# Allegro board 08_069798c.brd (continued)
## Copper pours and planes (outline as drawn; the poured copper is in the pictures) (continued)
EXT_VDDLDO on TOP: 35.07,63.68 35.07,61.61 34.81,61.36 32.97,61.36 32.84,61.23 32.84,60.41 33.03,60.21 36.59,60.21 36.72,60.34 36.72,63.68
EXT_VIO1V1 on TOP: 40.15,65.61 40.15,61.55 39.89,61.29 38.05,61.29 37.92,61.17 37.92,60.34 38.11,60.15 41.67,60.15 41.8,60.28 41.8,65.68 40.21,65.68
FMC_VADJ on TOP (solid shape): 80.78,42.63 81.13,42.63 81.13,42.17 79.84,42.17 79.61,42.4 79.61,42.72 79.78,42.89 80.53,42.89
FMC_VADJ on TOP (solid shape): 80.74,38.95 81.13,38.95 81.13,38.44 80.73,38.44 80.48,38.19 80.1,38.19 79.98,38.32 79.98,39.14 80.04,39.21 80.49,39.21
FMC_VADJ on TOP (solid shape): 80.74,27.41 81.13,27.41 81.13,26.9 80.73,26.9 80.48,26.65 80.1,26.65 79.98,26.78 79.98,27.6 80.04,27.67 80.49,27.67
FMC_VADJ on TOP (solid shape): 80.74,23.73 81.13,23.73 81.13,23.22 80.73,23.22 80.48,22.97 80.1,22.97 79.98,23.1 79.98,23.92 80.04,23.99 80.49,23.99
FMC_VADJ on BOTTOM (solid shape): 80.74,38.95 81.13,38.95 81.13,38.44 80.73,38.44 80.48,38.19 80.1,38.19 79.98,38.32 79.98,39.14 80.04,39.21 80.49,39.21
FMC_VADJ on BOTTOM (solid shape): 80.74,27.41 81.13,27.41 81.13,26.9 80.73,26.9 80.48,26.65 80.1,26.65 79.98,26.78 79.98,27.6 80.04,27.67 80.49,27.67
FMC_VADJ on BOTTOM (solid shape): 80.74,23.73 81.13,23.73 81.13,23.22 80.73,23.22 80.48,22.97 80.1,22.97 79.98,23.1 79.98,23.92 80.04,23.99 80.49,23.99
FMC_VADJ on TOP, BOTTOM: 81.13,35.27 80.74,35.27 80.49,35.53 80.04,35.53 79.98,35.47 79.98,34.64 80.1,34.51 80.48,34.51 80.73,34.76 81.13,34.76
FMC_VADJ on TOP, BOTTOM: 81.13,30.58 80.78,30.58 80.53,30.32 79.78,30.32 79.61,30.48 79.61,30.8 79.84,31.03 81.13,31.03
FMC_VADJ on TOP, BOTTOM: 81.13,46.3 80.74,46.3 80.49,46.56 80.04,46.56 79.98,46.5 79.98,45.67 80.1,45.55 80.48,45.55 80.73,45.8 81.13,45.8
FMC_VADJ on BOTTOM: 81.13,42.63 80.78,42.63 80.53,42.89 79.78,42.89 79.61,42.72 79.61,42.4 79.84,42.17 81.13,42.17
FMC_VADJ on L5_SECONDARY_POWER: outline of 127 points within 0.64,0.64 97.34,58.1 ; 1 cut-out
IOVDD on TOP: 70.14,35.48 70.14,35.93 70.02,36.05 70.02,36.82 70.09,36.88 71.04,36.88 71.17,36.75 71.17,36.43 71.04,36.31 70.72,36.31 70.59,36.18 70.59,35.99 70.5,35.89 70.5,35.48
IOVDD on BOTTOM: 70.09,35.74 72.12,35.74 72.12,36.56 76.44,36.56 76.44,40.82 73.9,40.82 73.9,37.39 70.78,37.39 70.78,37.58 70.09,37.58
IOVDD on L3_PRIMARY_POWER: 70.02,37.26 71.67,37.26 71.67,35.35 72.83,35.35 72.83,31.09 73.01,30.91 87.04,30.91 87.04,24.31 81.39,18.65 81.39,15.23 82.47,14.15 83.36,14.15 83.55,13.96 83.55,13.26 83.42,13.13 77.77,13.13 76.56,14.34 76.56,26.49 74.54,28.51 70.02,28.51
LDO_IN_VDD1V1 on TOP: 19.41,50.85 19.41,48.37 20.62,48.37 20.62,49.96 20.3,50.28 20.3,50.79 20.24,50.85
LDO_IN_VDD1V1 on TOP: 27.76,59.36 27.76,57.04 28.97,57.04 28.97,59.36
LDO_IN_VDD1V1 on TOP: 16.37,52.37 16.37,54.6 13.44,54.6 13.25,54.4 13.25,53.58 11.48,53.58 11.35,53.45 11.35,52.44 11.41,52.37
LDO_IN_VDD1V1 on BOTTOM: 13.51,52.5 13.51,55.67 13.76,55.93 25.83,55.93 25.86,55.9 25.86,55.96 28.05,58.15 29.13,58.15 29.19,58.09 29.19,56.75 26.49,54.06 24.14,54.06 24.18,54.02 20.81,54.02 20.68,53.9 20.68,48.56 20.62,48.5 19.41,48.5 19.41,53.9 19.54,54.02 19.48,54.09 14.84,54.09 14.71,53.96 14.71,52.44 13.57,52.44
LDO_IN_VDD1V1 on L5_SECONDARY_POWER: 29.07,56.82 29.07,58.85 27.35,60.56 16.62,60.56 13.44,57.39 13.44,52.63 14.02,52.06 14.97,52.06 15.1,52.18 15.1,56.5 16.87,58.28 26.65,58.28 27.6,57.33 27.6,56.75 27.73,56.63 28.87,56.63
LDO_IN_VDD3V3 on TOP: 51.8,18.27 51.8,17.26 51.86,17.19 53.07,17.19 53.13,17.26 53.7,17.26 53.83,17.13 53.83,16.11 53.89,16.05 54.66,16.05 54.78,16.18 54.78,17.64 54.15,18.27
LDO_IN_VDD3V3 on TOP: 58.02,14.27 58.02,12.3 61.89,12.3 61.89,14.27
LDO_IN_VDD3V3 on BOTTOM: 51.54,18.46 51.54,15.73 55.29,15.73 55.61,16.05 57.01,16.05 60.82,12.24 62.53,12.24 62.53,12.88 56.94,18.46
LDO_IN_VDDLDO on TOP: 32.78,59.36 32.78,57.07 33.99,57.07 33.99,59.36
LDO_IN_VDDLDO on TOP: 30.4,52.25 30.4,54.72 27.73,54.72 26.46,53.45 25.7,53.45 25.57,53.33 25.57,52.37 25.7,52.25
LDO_IN_VDDLDO on TOP: 33.38,50.79 33.38,48.31 34.59,48.31 34.59,50.79
LDO_IN_VDDLDO on BOTTOM: 27.48,53.64 27.48,52.5 27.6,52.37 28.81,52.37 28.81,53.77 28.75,53.83 33.19,53.83 33.45,53.58 33.45,48.37 34.78,48.37 34.78,55.74 34.68,55.83 34.68,58.18 34.02,58.85 32.81,58.85 32.62,58.66 32.62,55.87 32.37,55.87 32.3,55.8 28.94,55.8 27.41,54.28 27.41,53.71
LDO_IN_VIO1V1 on TOP: 44.11,52.25 44.11,54.72 40.62,54.72 39.35,53.45 39.35,52.5 39.61,52.25
LDO_IN_VIO1V1 on TOP: 37.99,59.36 37.99,57.1 39.19,57.1 39.19,59.36
LDO_IN_VIO1V1 on TOP: 47.1,50.79 47.1,48.31 48.31,48.31 48.31,50.79
LDO_IN_VIO1V1 on BOTTOM: 38.72,54.21 40.94,54.21 41.19,53.96 41.19,50.59 42.08,49.71 46.85,49.71 47.04,49.52 47.04,48.37 48.24,48.37 48.43,48.56 48.43,50.66 48.31,50.79 42.72,50.79 42.46,51.04 42.46,54.72 41.77,55.42 39.67,55.42 39.67,58.02 39.1,58.6 37.96,58.6 37.76,58.41 37.76,56.44 37.89,56.31 38.4,56.31 38.4,54.53
NEG_5V0 on BOTTOM: 39.99,21.26 39.99,20.05 42.27,20.05 42.27,21.26
NEG_5V0 on L5_SECONDARY_POWER: 82.21,18.72 82.21,16.56 82.12,16.46 82.12,14.11 81.96,13.96 80.37,13.96 79.55,14.78 79.55,14.97 78.82,15.7 76.59,15.7 76.5,15.8 76.5,15.86 75.36,17 67.61,17 67.42,16.81 43.23,16.81 41.45,18.59 41.45,18.65 40.88,19.23 40.88,21.38 42.21,21.38 42.21,19.92 43.16,18.97 76.75,18.97 76.88,18.84 77.13,18.84 77.42,19.13 77.83,18.72
OUT_VDDLDO on TOP: 35.42,59.42 36.43,59.42 36.56,59.29 36.56,55.99 36.18,55.61 35.61,55.61 35.42,55.8
OUT_VDDLDO on L5_SECONDARY_POWER: 35.22,58.53 35.22,51.86 42.08,45.01 44.75,45.01 44.75,47.55 44.56,47.74 42.34,47.74 42.21,47.61 36.94,52.88 36.94,58.41 36.81,58.53
PAD_A1 on TOP: 51.42,44.63 51.42,38.47 54.21,38.47 54.21,42.66 53.64,42.66 53.64,44.63
PAD_A6 on TOP: 51.42,30.34 51.42,24.18 54.21,24.18 54.21,28.37 53.64,28.37 53.64,30.34
REF on TOP: 70.47,31.29 68.88,31.29 68.88,30.27 70.47,30.27
REF on BOTTOM: 67.29,28.18 67.29,25.64 70.28,25.64 70.28,28.18
REF on L5_SECONDARY_POWER: 67.93,32.69 69.71,32.69 69.71,31.69 70.85,31.69 70.78,31.62 70.78,21.07 57.45,21.07 57.45,24.31 67.55,24.31 67.55,29.26 67.93,29.64
REF3P on TOP: 71.48,15.61 75.17,15.61 75.17,17.07 71.48,17.07 71.48,16.81 69.58,16.81 69.58,15.92 71.48,15.92
SNS33 on TOP: 41.73,12.46 41.73,9.99 42.94,9.99 42.94,12.46
SNS33 on L3_PRIMARY_POWER: 69.64,32.5 69.64,28.32 69.7,28.19 69.83,28.13 74.2,28.13 75.99,26.34 75.99,13.83 77.13,12.69 88.06,12.69 88.06,8.3 84.12,8.3 81.2,11.22 75.99,11.22 73.45,8.68 42.4,8.68 41.57,9.51 41.57,12.05 41.89,12.37 42.78,12.37 43.19,11.95 43.19,10.53 43.96,9.76 46.78,9.76 47.04,10.02 70.78,10.02 74.28,13.51 74.28,22.91 73.77,23.42 71.23,23.42 71.23,24.43 67.17,24.43 66.97,24.62 66.97,32.62 69.51,32.62
UNNAMED_7_ADP7118V2_I90_SENSE on TOP: 78.34,53.45 78.34,52.69 83.42,52.69 83.42,53.83 81.45,53.83 81.45,53.45
UNNAMED_8_ADA49451_I81__4 on TOP: 35.22,37.7 35.22,34.08 36.24,34.08 36.24,37.7
UNNAMED_8_ADA49451_I81__5 on TOP: 36.27,28.34 36.27,31.96 35.25,31.96 35.25,28.34
UNNAMED_8_ADLT6236_I15__1 on BOTTOM: 16,24.79 16,19.56 16.24,19.33 16.87,19.33 17.15,19.6 17.15,24.79
UNNAMED_8_ADLT6236_I15_OUT on BOTTOM: 17.74,24.79 17.74,19.56 17.97,19.33 18.61,19.33 18.88,19.6 18.88,23.39 20.24,23.39 20.37,23.52 20.37,24.66 20.24,24.79
UNNAMED_8_ADLT6236_I33__1 on BOTTOM: 16,39.99 16,34.76 16.24,34.53 16.87,34.53 17.15,34.8 17.15,39.99
UNNAMED_8_ADLT6236_I33_OUT on BOTTOM: 17.74,39.99 17.74,34.76 17.97,34.53 18.61,34.53 18.88,34.8 18.88,38.59 20.24,38.59 20.37,38.72 20.37,39.86 20.24,39.99
UNNAMED_11_CAP_I205_N1 on TOP: 54.97,14.21 54.97,10.84 51.93,10.84 51.93,13.64 51.42,14.15 51.42,16.5 51.86,16.94 53.7,16.94 53.7,16.18 53.64,16.11 53.26,16.11 53.07,16.3 53.07,16.43 52.12,16.43 52.12,14.21
UNNAMED_11_CAP_I213_N1 on TOP: 36.37,53.2 37.13,52.44 37.13,48.44 35.16,48.44 34.84,48.75 34.84,50.66 34.97,50.79 35.48,50.79 35.61,50.66 35.61,49.07 36.69,49.07 36.75,49.13 36.75,50.4 36.62,50.53 36.62,51.93 36.18,52.37 33.7,52.37 33.7,54.53 33.8,54.63 33.8,56.47 34.02,56.69 34.59,56.69 34.84,56.44 34.84,54.72 36.37,54.72
UNNAMED_11_CAP_I221_N1 on TOP: 19.48,54.21 19.48,52.5 21.38,52.5 21.32,52.44 21.32,51.8 21.45,51.67 22.08,51.67 22.08,51.48 22.27,51.29 22.27,50.02 22.4,49.9 22.46,49.9 22.46,48.75 22.4,48.69 21.25,48.69 21.19,48.75 21.19,50.91 20.75,50.91 20.75,48.37 20.87,48.25 22.72,48.25 22.84,48.37 22.84,50.15 22.91,50.21 22.91,53.2 23,53.29 22.33,53.96 22.33,54.21 20.49,54.21 20.49,55.8 20.3,55.99 19.6,55.99 19.54,55.93 19.6,55.87 19.6,54.21
UNNAMED_11_CAP_I227_N1 on TOP: 49.96,54.09 49.96,53.39 50.97,52.37 50.97,48.75 48.56,48.75 48.43,48.88 48.43,50.91 48.88,50.91 49.13,50.66 49.13,49.32 50.4,49.32 50.4,51.55 49.58,52.37 47.29,52.37 47.29,55.8 47.48,55.99 48.37,55.99 48.69,55.67 48.69,54.09
UNNAMED_12_CAP_I88_N1 on BOTTOM: 31.73,17.77 31.73,16.3 32.37,16.3 32.62,16.05 32.62,12.88 34.46,12.88 35.16,13.57 35.16,14.78 35.1,14.84 34.4,14.84 34.4,13.45 34.21,13.26 33.26,13.26 33.26,16.11 33.45,16.3 36.37,16.3 36.37,18.21 35.16,18.21 35.16,17.77

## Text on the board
Ref Des/Assembly Bottom: 2 | 1 | 3
Ref Des/Silkscreen Bottom: 1 | 3 | DCO | N | P | GPIO1 | GPIO0 | GPIO2 | GPIO3 | SDI | SCK | CSB
User.Comments: FOR SCREW AND STANDOFF INSTALLATION. | SOLDER FILLET BOARD ETCH TO | CONNECTOR TOP AND BOTTOM. | ETCH TO EDGE 3 MILS. | 2 PLACES | SEE NOTE 5 | (2 PLACES) | SEE NOTE 4 | 7.    BOARDS TO BE SHIPPED SINGULATED AFTER ASSEMBLY PROCESS. | 5.    INSTALL SCREW (M025339) ON PRIMARY SIDE AND | AD4080 WILL BE SUPPLIED AND INSTALLED ON IT. | 4.    U22 IS A COMBO FOOTPRINT. | SMOOTHEN EDGES AND FREE FROM BURRS AFTER DEPANELIZATION PROCESS. | STANDOFF (M025474) ON THE SECONDARY SIDE.
Ref Des/Assembly Top: 1
Ref Des/Silkscreen Top: N | DCO | P | CLK | CNV | I1 | I3 | I5 | I7 | 1 | VADJ | DGND | PBIO | I2 | I4 | I6 | I8 | I0 | AGND | 2 | 3 | 4 | EVAL-AD4080   FMCZ | VDD | C | A | EXT | 7
DIMENSION: - | " " | 0 | X | Y | 0.0328 | 0.2327 | (REF) | 0.3862 | 0.1863 | 0.6190 | 0.3190 | +1/-1 | +2/-0 | DIA MAX | SEE NOTE 15 | SEE NOTE 16 | "TRUE POSITION" | SEE DETAIL W
PAGE_OUTLINE: B | CHANGES AS PER ECR-109154 | 08SEP22 | D. SLOAN | CUSTOMER EVAL BOARD Z
User.11: 3 | 2 | 1 | C | A
User.12: 2 | 1 | 3 | 40
User.15: ENIG (ELECTROLESS NICKEL IMMERSION GOLD) | PER IPC-4552 LATEST REVISION. | CRITICAL HOLE AND SLOT FINISHED SIZE AND POSITION SPECIFIED IN DETAIL W. | 16.    THRU VIAS FILLED WITH NON-CONDUCTIVE EPOXY AND PLATED OVER. | 17.    CRITICAL DRILLED HOLE TO IMAGED FEATURE TRUE POSITION OF +/-.001 INCH | FROM PRIMARY SIDE COPPER IS REQUIRED. HOLE SIZE AND POSITION MUST BE | VERIFIED AND MEASURED AGAINST THE VALUES SPECIFIED IN DETAIL W. | SEE DRILL TABLE "TRUE POSITION", 33 MIL NON-PLATED (QTY 2) | TO BE DRILLED FROM THE PRIMARY SIDE OF THE BOARD | IN A SECONDARY DRILLING OPERATION. | 18.    INCLUDE IN CERTIFICATE OF COMPLIANCE AND QA REPORT THE MEASUREMENT FOR | COPLANAR ON PRIMARY SIDE WITHIN .001 INCH PRIOR TO FINAL PLATING. | 19.    BOARDS TO BE SHIPPED IN ARRAY AND KEEP INTACT. | 15.    THRU VIAS FILLED WITH NON-CONDUCTIVE EPOXY AND PLATED OVER. | PANELED SOLDER PASTE STENCIL SHOULD BE SENT TO THE CUSTOMER. | PANEL TO BE SUBJECTED TO CUSTOMER'S APPROVAL | NOTE: ALL IMPEDANCE TOLERANCE +/-10% | LAYER | L1 | L3 | L6 | SE = SINGLE ENDED, DP = DIFFERENTIAL PAIR | 100 OHMS DP | 50 OHMS SE | IMPEDANCE | REFERENCE | L2 | L5 | LINE WIDTH | 5MILS | 7MILS | SPACE | 6MILS | N/A | IMPEDANCE TABLE
User.23: 08-      -07 | L2 GND
User.24: 08-      -08 | L3 PRIMARY POWER
User.25: 08-      -09 | L4 SECONDARY POWER
User.26: 08-      -10 | L5 GND
User.27: 08-      -09 | L4 SECONDARY_POWER
User.28: 08-      -10 | L5 GND
User.30: SIGNAL CHAIN POWER SUPPLY CIRCUITS | PAGE 4 | PRECISION SIGNAL CONDITIONING | PAGE 2 | COMMON MODE BUFFER CKT | PAGE 5 | VOLTAGE REFERENCE CIRCUITS | SUPPLY  SEQ CIRCUITS | REFERENCE CIRCUIT | PAGE 3 | CLK CKT | PAGE 6 | INPUT NETWORK
User.45: FIGURE | SIZE | 6.0 | 10.0 | 14.0 | 40.0 | 45.0 | 50.0 | 55.0 | 60.0 | 47.0 | 125.0 | PLATED | NON-PLATED | FINISHED HOLES IN MILS | ALL UNITS ARE IN MILS | QTY | 33 | 34 | 4 | 1102 | 36 | 24 | 1 | 2 | TOLERANCE/NOTES
